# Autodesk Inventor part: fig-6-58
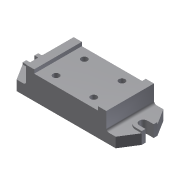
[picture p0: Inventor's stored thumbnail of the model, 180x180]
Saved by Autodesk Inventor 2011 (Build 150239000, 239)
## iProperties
Shininess: 77.0
Angle Display Precision: 2
Document Length Units: 11269
Document Angle Units: 11279
Document Time Units: 11290
Document Mass Units: 11283
Document Length Units Precision: 3
Document Angle Units Precision: 2
Created: 2001-12
Part Number: fig-6-58
Document SubType Name: Modeling
Designer: Renu Muthoo
Density: 1 g/cm^3
Density: 0.0
Volumn: 0.0
Area: 0.0
PropertySet Name: Model Information
Control State: 0
Master: False
Checked Out: False
Author: Renu Muthoo
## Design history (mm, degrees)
sketch "Sketch3"
  geometry: L1 (-59.119, -24.322)-(-59.119, 19.678); L2 (-59.119, 19.678)-(-46.119, 19.678); L3 (-46.119, 19.678)-(-46.119, 13.678); L4 (-46.119, 13.678)-(55.881, 13.678); L5 (55.881, 13.678)-(55.881, 19.678); L6 (55.881, 19.678)-(68.881, 19.678); L7 (68.881, 19.678)-(68.881, -24.322); L8 (68.881, -24.322)-(-59.119, -24.322)
  constraints: 16 end point, 2 equal length
  dimensions: "d10" = 13 distance of L1.end L2.end; "d11" = 102 distance of L3.end L4.end; "d13" = 44 distance between parallel lines of L2 L8; "d14" = 6 distance of L2.end L3.end
extrude "Extrusion1" new body sketch "Sketch3" distance "d15" = 76; taper "d16" = 0 deg
sketch "Sketch4"
  geometry: L1 (0, 0)-(0, 76) reference; L2 (0, 76)-(-15, 76); L3 (-15, 76)-(-31, 50.5); L4 (-31, 50.5)-(-31, 44.5); L5 (-31, 44.5)-(-21, 44.5); L6 (-21, 31.5)-(-31, 31.5); L7 (-31, 31.5)-(-31, 25.5); L8 (-31, 25.5)-(-15, 0); L9 (-15, 0)-(0, 0); L10 (128, 76)-(0, 76) reference; L11 (0, 0)-(128, 0) reference; A1 r 6.5 centre (-21, 38) between (-21, 31.5) and (-21, 44.5)
  constraints: 16 end point, 4 equal length, 3 collinear, 3 parallel, 2 perpendicular, 2 point on circle, 2 tangent, 1 centre point
  dimensions: "d17" = 13 distance between parallel lines of L6 L5; "d18" = 25 distance of L3.end L7.end; "d19" = 10 distance of L6.start L6.end; "d20" = 15 distance of L8.end L1.start; "d21" = 16 horizontal distance of L7.end L8.end
extrude "Extrusion2" join sketch "Sketch4" distance "d22" = 16; taper "d23" = 0 deg
sketch "Sketch5"
  geometry: L1 (-159, 44.5)-(-159, 50.5) reference; L2 (-149, 44.5)-(-159, 44.5) reference; L3 (-159, 31.5)-(-149, 31.5) reference; L4 (-159, 25.5)-(-159, 31.5) reference; L5 (-159, 25.5)-(-149, 25.5); L6 (-149, 50.5)-(-159, 50.5); A1 r 6.5 centre (-149, 38) between (-149, 31.5) and (-149, 44.5) reference; A2 r 12.5 centre (-149, 38) between (-149, 25.5) and (-149, 50.5)
  constraints: 4 end point, 2 point on circle, 2 tangent, 1 centre point, 1 parallel, 1 perpendicular
extrude "Extrusion3" join sketch "Sketch5" distance "d24" = 19; taper "d25" = 0 deg
workplane "Work Plane1"
mirror "Mirror1"
fillet "Fillet1" dims "d27" = 4
sketch "Sketch6"
  geometry: L1 (0, 0)-(0, 76) reference; L2 (0, 0)-(102, 0) reference; 1 further point
  dimensions: "d28" = 20 distance from line of L1 point (20, 15); "d29" = 15 distance from line of L2 point (20, 15)
hole "Hole1" sketch "Sketch6" at (20, 15) diameter "d30" = 10; stored, may be unused: countersink angle "d34" = 82 deg, drill point angle "d36" = 118 deg; dims "d31" = 6, "d32" = 4, "d33" = 2, "d35" = 15
sketch "Sketch7"
  geometry: C1 r 5 at (20, 15) reference; 3 further points
  constraints: 4 other
pattern_linear "Rectangular Pattern2" dims "d45" = 45
body "Solid1"
other parameters: "d26" = -64
